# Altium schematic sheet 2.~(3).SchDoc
size 420 x 297 mm
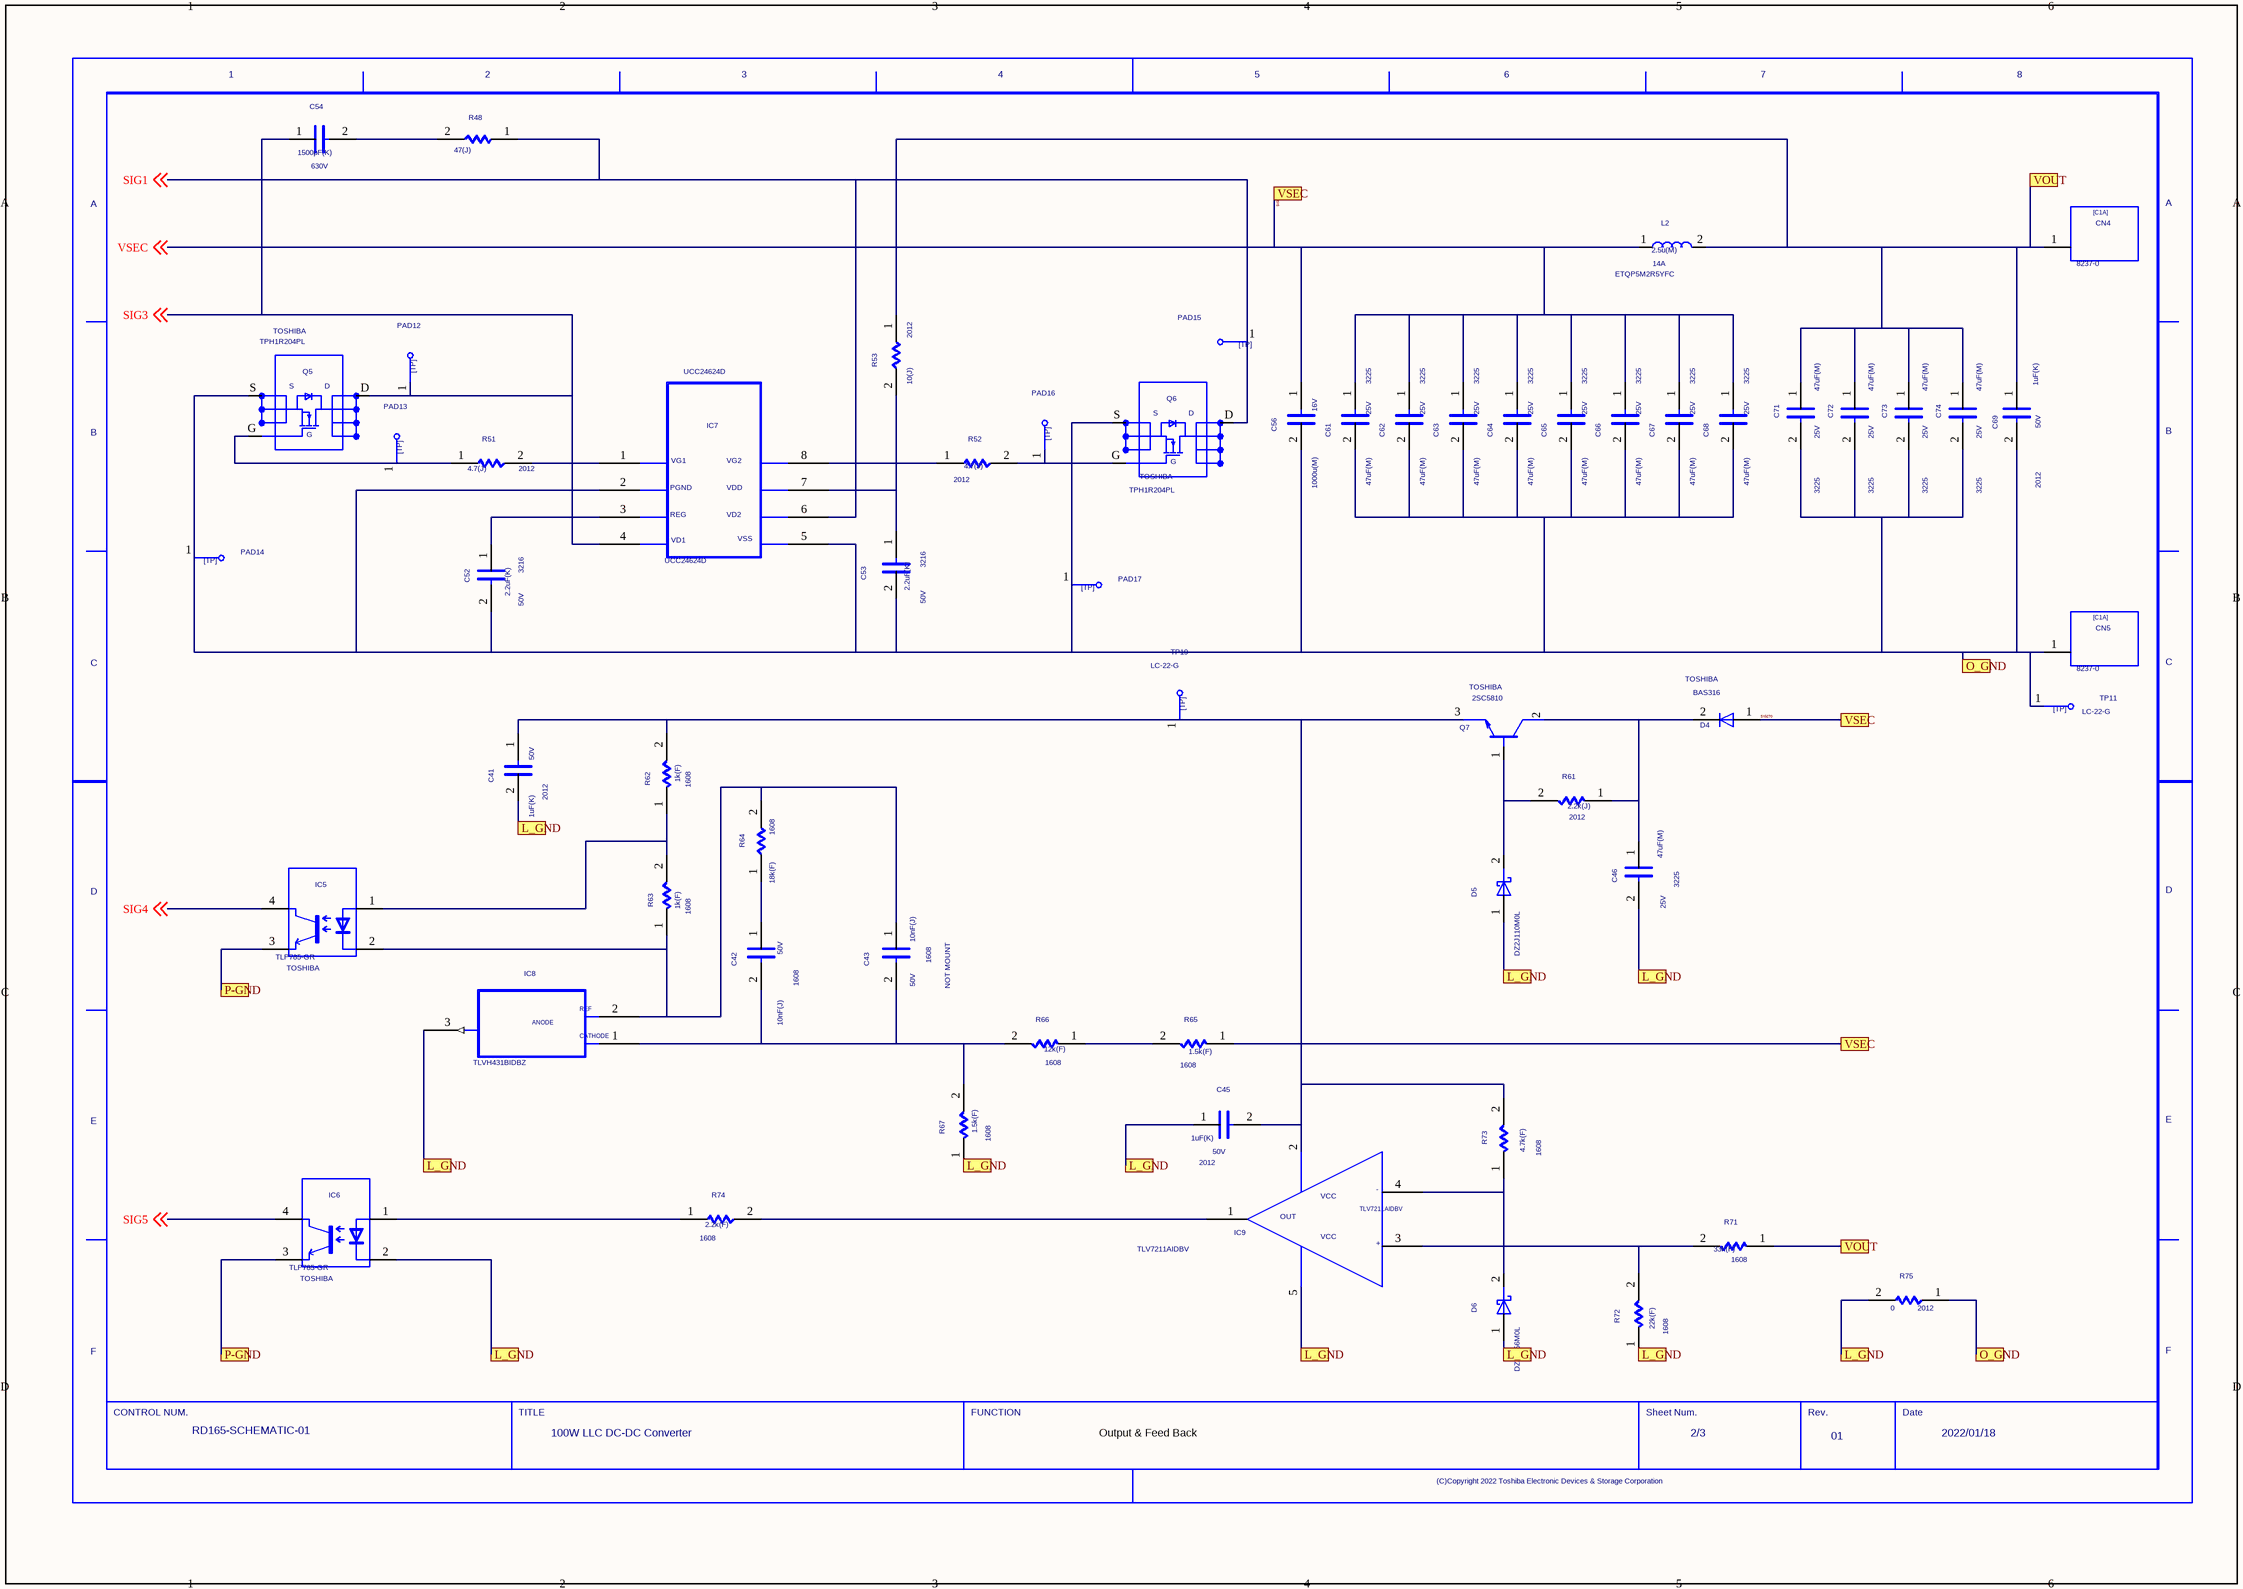
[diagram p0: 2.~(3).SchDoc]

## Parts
C41  SIZECODESMD: 2012  VAL2: 50V  VAL1: 1uF(K)  (hidden comment: C)
C42  SIZECODESMD: 1608  VAL2: 50V  VAL1: 10nF(J)  (hidden comment: C)
C43  NOTMOUNT: NOT MOUNT  SIZECODESMD: 1608  VAL2: 50V  VAL1: 10nF(J)  (hidden comment: C)
C45  SIZECODESMD: 2012  VAL2: 50V  VAL1: 1uF(K)  (hidden comment: C)
C46  SIZECODESMD: 3225  VAL2: 25V  VAL1: 47uF(M)  (hidden comment: C)
C52  SIZECODESMD: 3216  VAL2: 50V  VAL1: 2.2uF(K)  (hidden comment: C)
C53  SIZECODESMD: 3216  VAL2: 50V  VAL1: 2.2uF(K)  (hidden comment: C)
C54  VAL2: 630V  VAL1: 1500pF(K)  (hidden comment: C)
C56  VAL2: 16V  VAL1: 1000u(M)  (hidden comment: C)
C61  SIZECODESMD: 3225  VAL2: 25V  VAL1: 47uF(M)  (hidden comment: C)
C62  SIZECODESMD: 3225  VAL2: 25V  VAL1: 47uF(M)  (hidden comment: C)
C63  SIZECODESMD: 3225  VAL2: 25V  VAL1: 47uF(M)  (hidden comment: C)
C64  SIZECODESMD: 3225  VAL2: 25V  VAL1: 47uF(M)  (hidden comment: C)
C65  SIZECODESMD: 3225  VAL2: 25V  VAL1: 47uF(M)  (hidden comment: C)
C66  SIZECODESMD: 3225  VAL2: 25V  VAL1: 47uF(M)  (hidden comment: C)
C67  SIZECODESMD: 3225  VAL2: 25V  VAL1: 47uF(M)  (hidden comment: C)
C68  SIZECODESMD: 3225  VAL2: 25V  VAL1: 47uF(M)  (hidden comment: C)
C69  SIZECODESMD: 2012  VAL2: 50V  VAL1: 1uF(K)  (hidden comment: C)
C71  SIZECODESMD: 3225  VAL2: 25V  VAL1: 47uF(M)  (hidden comment: C)
C72  SIZECODESMD: 3225  VAL2: 25V  VAL1: 47uF(M)  (hidden comment: C)
C73  SIZECODESMD: 3225  VAL2: 25V  VAL1: 47uF(M)  (hidden comment: C)
C74  SIZECODESMD: 3225  VAL2: 25V  VAL1: 47uF(M)  (hidden comment: C)
CN4  VAL3: 8237-0  (hidden comment: C1A)
CN5  VAL3: 8237-0  (hidden comment: C1A)
D4  USERCOMPTEXT3: TOSHIBA  VAL3: BAS316  (hidden comment: D)
D5  VAL3: DZ2J110M0L  (hidden comment: SBD)
D6  VAL3: DZ2J056M0L  (hidden comment: SBD)
IC5  USERCOMPTEXT3: TOSHIBA  (hidden comment: TLP785-GR)
IC6  USERCOMPTEXT3: TOSHIBA  (hidden comment: TLP785-GR)
IC7  UCC24624D
IC8  VAL3: TLVH431BIDBZ  (hidden comment: HC086_GATE)
IC9  TLV7211AIDBV
L2  VAL3: ETQP5M2R5YFC  VAL2: 14A  VAL1: 2.5u(M)  (hidden comment: L)
PAD12  TP  (value not drawn)
PAD13  TP  (value not drawn)
PAD14  TP  (value not drawn)
PAD15  TP  (value not drawn)
PAD16  TP  (value not drawn)
PAD17  TP  (value not drawn)
Q5  USERCOMPTEXT3: TOSHIBA  (hidden comment: TPH1R204PL)
Q6  USERCOMPTEXT3: TOSHIBA  (hidden comment: TPH1R204PL)
Q7  USERCOMPTEXT3: TOSHIBA  (hidden comment: 2SC5810)
R48  VAL1: 47(J)  (hidden comment: R)
R51  SIZECODESMD: 2012  VAL1: 4.7(J)  (hidden comment: R)
R52  SIZECODESMD: 2012  VAL1: 4.7(J)  (hidden comment: R)
R53  SIZECODESMD: 2012  VAL1: 10(J)  (hidden comment: R)
R61  SIZECODESMD: 2012  VAL1: 2.2k(J)  (hidden comment: R)
R62  SIZECODESMD: 1608  VAL1: 1k(F)  (hidden comment: R)
R63  SIZECODESMD: 1608  VAL1: 1k(F)  (hidden comment: R)
R64  SIZECODESMD: 1608  VAL1: 18k(F)  (hidden comment: R)
R65  SIZECODESMD: 1608  VAL1: 1.5k(F)  (hidden comment: R)
R66  SIZECODESMD: 1608  VAL1: 12k(F)  (hidden comment: R)
R67  SIZECODESMD: 1608  VAL1: 1.5k(F)  (hidden comment: R)
R71  SIZECODESMD: 1608  VAL1: 33k(F)  (hidden comment: R)
R72  SIZECODESMD: 1608  VAL1: 22k(F)  (hidden comment: R)
R73  SIZECODESMD: 1608  VAL1: 4.7k(F)  (hidden comment: R)
R74  SIZECODESMD: 1608  VAL1: 2.2k(F)  (hidden comment: R)
R75  SIZECODESMD: 2012  VAL1: 0  (hidden comment: R)
TP11  VAL3: LC-22-G  (hidden comment: TP)
TP19  VAL3: LC-22-G  (hidden comment: TP)
U?  DATE: 2022/01/18  REVISION: 01  SHEETNUMBER: 2/3  TITLE: 100W LLC DC-DC Converter  DRAWINGNUMBER: RD165-SCHEMATIC-01  (hidden comment: WAKU_DEF100)

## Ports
L_GND, O_GND, P-GND, VOUT, VSEC

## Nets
DN000026: C53.1 IC7.7 R53.2
O_GND: C52.2 C53.2 C56.2 C61.2 C62.2 C63.2 C64.2 C65.2 C66.2 C67.2 C68.2 C69.2 C71.2 C72.2 C73.2 C74.2 CN5.1 IC7.2 IC7.5 PAD14.1 PAD17.1 Q5.S Q6.S R75.1 TP11.1 ; port O_GND
P-GND: IC5.3 IC6.3 ; port P-GND
SIG1: IC7.6 PAD15.1 Q6.D R48.1 ; off-sheet SIG1
SIG3: C54.1 IC7.4 PAD12.1 Q5.D ; off-sheet SIG3
SIG4: IC5.4 ; off-sheet SIG4
SIG5: IC6.4 ; off-sheet SIG5
SIG140: C41.2 C45.1 C46.2 D5.1(A) D6.1(A) IC6.2 IC8.3(A2) IC9.5 R67.1 R72.1 R75.2 ; port L_GND  [also labelled SIG142, SIG149, SIG150, SIG152, SIG156, SIG158, SIG226]
SIG144: C43.1 IC5.2 IC8.2(A0) R63.1 R64.2
SIG154: IC9.3 R71.2 R72.2
SIG160: D5.2(C) Q7.1 R61.2
SIG162: C46.1 D4.2(C) Q7.2 R61.1
SIG166: C52.1 IC7.3
SIG167: IC7.1 R51.2
SIG170: IC7.8 R52.1
SIG172: PAD16.1 Q6.G R52.2
SIG184: IC9.1 R74.2
SIG185: IC6.1 R74.1
SIG210: PAD13.1 Q5.G R51.1
SIG214: C56.1 C61.1 C62.1 C63.1 C64.1 C65.1 C66.1 C67.1 C68.1 D4.1(A) L2.1 R65.1 ; off-sheet VSEC, port VSEC  [also labelled SIG270, VSEC]
SIG215: C69.1 C71.1 C72.1 C73.1 C74.1 CN4.1 L2.2 R53.1 R71.1 ; port VOUT
SIG216: R65.2 R66.1
SIG222: D6.2(C) IC9.4 R73.1
SIG225: C42.2 C43.2 IC8.1(A1) R66.2 R67.2
SIG242: IC5.1 R62.1 R63.2
SIG243: C41.1 C45.2 IC9.2 Q7.3 R62.2 R73.2 TP19.1
SIG244: C42.1 R64.1
SIG247: C54.2 R48.2

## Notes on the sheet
- Output & Feed Back

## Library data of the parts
C41 = C#1: OriginalSymbolOrigin: (2540,7620); CaptureCellPackProp: C##1; RATEDVOLTAGE: 50; MAXGCOUNT: 1; OUMEMAKER: TDK ＴＤＫ; QUADMODEL: CON_1U; FNLEADFREETHET1GT2GMCTH1: 3_2_N; OUMECLASSIFICATION: セラミックコンデンサ; CDBNAME: Chip2012_GS_1; NOMINALCAPACITA: 1u; PMPRODUCTSTYPEG: DA; OUMEMAKERKATAMEI: CGA4J3X7R1H105KT@@; CAPACITANCETOLE: K; CDMASTERCADCELG: KC0159; ADSMODELNAME: s_CGA4J3X7R1H105KT@@
C42 C43 = C: OriginalSymbolOrigin: (2540,7620); RATEDVOLTAGE: 50; MAXGCOUNT: 1; OUMEMAKER: TDK ＴＤＫ; QUADMODEL: CON_10N; FNLEADFREETHET1GT2GMCTH1: 3_2_N; OUMECLASSIFICATION: セラミックコンデンサ; CDBNAME: Chip1608_GS_1; NOMINALCAPACITA: 10n; PMPRODUCTSTYPEG: HEV; OUMEMAKERKATAMEI: CGA3E2C0G1H103JT@@; CAPACITANCETOLE: J; CDMASTERCADCELG: KC0134; ADSMODELNAME: s_CGA3E2C0G1H103JT@@
C45 C69 = C: OriginalSymbolOrigin: (2540,7620); RATEDVOLTAGE: 50; MAXGCOUNT: 1; OUMEMAKER: TDK ＴＤＫ; QUADMODEL: CON_1U; FNLEADFREETHET1GT2GMCTH1: 3_2_N; OUMECLASSIFICATION: セラミックコンデンサ; CDBNAME: Chip2012_GS_1; NOMINALCAPACITA: 1u; PMPRODUCTSTYPEG: DA; OUMEMAKERKATAMEI: CGA4J3X7R1H105KT@@; CAPACITANCETOLE: K; CDMASTERCADCELG: KC0159; ADSMODELNAME: s_CGA4J3X7R1H105KT@@
C46 = C: OriginalSymbolOrigin: (2540,7620); RATEDVOLTAGE: 6.3; MAXGCOUNT: 1; OUMEMAKER: MRT 村田製作所; QUADMODEL: CON_47U; FNLEADFREETHET1GT2GMCTH1: 3_0_N; OUMECLASSIFICATION: セラミックコンデンサ; CDBNAME: Chip3225_GS; NOMINALCAPACITA: 47u; PMPRODUCTSTYPEG: HEV; OUMEMAKERKATAMEI: GCM32ER70J476ME19L@@; CAPACITANCETOLE: M; CDMASTERCADCELG: KC0138; ADSMODELNAME: s_GCM32ER70J476ME19L@@
C52 = C: OriginalSymbolOrigin: (2540,7620); RATEDVOLTAGE: 50; MAXGCOUNT: 1; OUMEMAKER: MRT 村田製作所; QUADMODEL: CON_2.2U; FNLEADFREETHET1GT2GMCTH1: 3_2_N; OUMECLASSIFICATION: セラミックコンデンサ; CDBNAME: Chip3216_GS_1; NOMINALCAPACITA: 2.2u; PMPRODUCTSTYPEG: HEV; OUMEMAKERKATAMEI: GCM31CR71H225KA55L@@; CAPACITANCETOLE: K; CDMASTERCADCELG: KC0137; ADSMODELNAME: s_GCM31CR71H225KA55L@@
C53 = C#1: OriginalSymbolOrigin: (2540,7620); CaptureCellPackProp: C##1; RATEDVOLTAGE: 50; MAXGCOUNT: 1; OUMEMAKER: MRT 村田製作所; QUADMODEL: CON_2.2U; FNLEADFREETHET1GT2GMCTH1: 3_2_N; OUMECLASSIFICATION: セラミックコンデンサ; CDBNAME: Chip3216_GS_1; NOMINALCAPACITA: 2.2u; PMPRODUCTSTYPEG: HEV; OUMEMAKERKATAMEI: GCM31CR71H225KA55L@@; CAPACITANCETOLE: K; CDMASTERCADCELG: KC0137; ADSMODELNAME: s_GCM31CR71H225KA55L@@
C54 = C: OriginalSymbolOrigin: (2540,7620); CDBNAME: ECQE2**3*F_PN
C56 = C#1: OriginalSymbolOrigin: (2540,7620); CaptureCellPackProp: C##1; CDBNAME: PCR1****MCL1GS_NC
C61-C68 = C#1: OriginalSymbolOrigin: (2540,7620); CaptureCellPackProp: C##1; RATEDVOLTAGE: 6.3; MAXGCOUNT: 1; TEMPCHARACTERI2: B; OUMEMAKER: TYD 太陽誘電; QUADMODEL: CON_47U; FNLEADFREETHET1GT2GMCTH1: 3_0_N; OUMECLASSIFICATION: セラミックコンデンサ; CDBNAME: Chip3225_GS; NOMINALCAPACITA: 47u; PMPRODUCTSTYPEG: SV1; OUMEMAKERKATAMEI: JMK325BJ476MM-T; CAPACITANCETOLE: M; CDMASTERCADCELG: DC903A; ADSMODELNAME: s_JMK325BJ476MM_T
C71-C74 = C: OriginalSymbolOrigin: (2540,7620); RATEDVOLTAGE: 6.3; MAXGCOUNT: 1; TEMPCHARACTERI2: B; OUMEMAKER: TYD 太陽誘電; QUADMODEL: CON_47U; FNLEADFREETHET1GT2GMCTH1: 3_0_N; OUMECLASSIFICATION: セラミックコンデンサ; CDBNAME: Chip3225_GS; NOMINALCAPACITA: 47u; PMPRODUCTSTYPEG: SV1; OUMEMAKERKATAMEI: JMK325BJ476MM-T; CAPACITANCETOLE: M; CDMASTERCADCELG: DC903A; ADSMODELNAME: s_JMK325BJ476MM_T
CN4 CN5 = C1A: OUMEPARTTYPE: CN; SAVEAREA0: -2398,-158,22444,15662; SAVECOUNT: 23; TIME: 13:28:28; UPDATEUSER: 19910145; UPDATETIME: 08:46:11; OriginalSymbolOrigin: (5080,12700); RATEDCURRENT: 0; MAXGCOUNT: 1; OUMEMAKER: AMP タイコエレクトロニクスアンプ; FNLEADFREETHET1GT2GMCTH1: N_N_N; OUMECLASSIFICATION: プリント板用角形コネクタ; CDBNAME: 8237-0-05-**-00-00-03-0_ML; OUMEMAKERKATAMEI: 87220-1; CDMASTERCADCELG: CUK0165
D4 = D: SAVEAREA0: -225,-91,12804,7836; SAVECOUNT: 3; TIME: 14:49:55; UPDATEUSER: 19870035; UPDATETIME: 14:20:16; OriginalSymbolOrigin: (5080,5080); CDBNAME: BAS316_TS_A
D5 = SBD: SAVEAREA0: -4630,-153,17114,13055; TIME: 14:49:55; UPDATEUSER: fukuda-y; UPDATETIME: 08:16:22; SAVECOUNT: 9; OriginalSymbolOrigin: (5080,5080); CDBNAME: DZ2J110M0L_PN_A
D6 = SBD: SAVEAREA0: -4630,-153,17114,13055; TIME: 14:49:55; UPDATEUSER: fukuda-y; UPDATETIME: 08:16:22; SAVECOUNT: 9; OriginalSymbolOrigin: (5080,5080); CDBNAME: DZ2J056*0L_PN_A
IC5 IC6 = TLP785-GR: SAVEAREA0: -14986,-1554,37270,22534; TIME: 18:29:30; UPDATEUSER: t5459927; UPDATETIME: 17:04:25; SAVECOUNT: 2; OriginalSymbolOrigin: (5080,17780); CDBNAME: TLP785_TS_1
IC7 = UCC24624D: TIME: 09:07:35; UPDATEUSER: t5459927; UPDATETIME: 09:15:01; SAVECOUNT: 2; SAVEAREA0: -23382,-806,66635,38817; OriginalSymbolOrigin: (7620,35560); CDBNAME: UCC24624D*_TI
IC8 = HC086_GATE: OUMEPARTTYPE: IC; SAVEAREA0: -52989,-44408,93321,62857; TIME: 17:36:35; UPDATEUSER: t5459927; UPDATETIME: 16:48:34; SAVECOUNT: 2; OriginalSymbolOrigin: (7620,15240); MAXGCOUNT: 4; OUMEMAKER: TSB 東芝; GCOUNT: 1; MOUNTINGFORMSMD: SMD; FNLEADFREETHET1GT2GMCTH1: N_N_N; OUMECLASSIFICATION: CMOSロジック; CDBNAME: TLVH43***DBZ*_TI; PROCESS: 74HC; OUMEMAKERKATAMEI: TC74HC86F; CDMASTERCADCELG: DI830B
IC9 = TLV7211AIDBV: SAVECOUNT: 19; SAVEAREA0: -11523,-10867,52370,35975; TIME: 20:02:00; UPDATEUSER: t5459927; UPDATETIME: 08:40:37; OriginalSymbolOrigin: (7620,25400); CDBNAME: TLV7211AIDBVR_TI
L2 = L: OriginalSymbolOrigin: (2540,5080); CDBNAME: ETQP5M***YFC_PN
PAD12-PAD17 = TP: TIME: 16:12:21; UPDATEUSER: fukuda-y; UPDATETIME: 16:18:11; SAVECOUNT: 2; SAVEAREA0: -242,-92,12810,7836; OriginalSymbolOrigin: (0,7620); CDBNAME: TP_I_TH0.5_LC1.1_RC1.2_GS
Q5 Q6 = TPH1R204PL: SAVEAREA0: -12325,8914,25768,24851; TIME: 18:57:44; UPDATEUSER: t5459927; UPDATETIME: 15:06:39; SAVECOUNT: 19; OriginalSymbolOrigin: (2540,20320); CDBNAME: TPH1R204PL_TS_A
Q7 = 2SC5810: DEVICENAME: 2SC2712-Y; SAVECOUNT: 8; SAVEAREA0: -35656,-18339,48402,18661; TIME: 17:21:57; UPDATEUSER: t5459927; UPDATETIME: 15:35:42; OriginalSymbolOrigin: (2540,10160); CDBNAME: 2SC5810_TS
R48 = R: OriginalSymbolOrigin: (5080,5080); VAL2: 1W; CDBNAME: MOS1C****_GS_1
R51 R52 = R: OriginalSymbolOrigin: (5080,5080); MAXGCOUNT: 1; OUMEMAKER: HDK 北陸電気工業; QUADMODEL: RES_4.7; MOUNTINGFORMSMD: SMD; FNLEADFREETHET1GT2GMCTH1: N_N_N; OUMECLASSIFICATION: 表面実装用固定抵抗器; CDBNAME: Chip2012_GS_1; RESISTANCETOLER: J; POWERRATING: 100m; OUMEMAKERKATAMEI: CR1/10 4R7JV; NOMINALRESISTAN: 4.7; VAL2: 400mW; CDMASTERCADCELG: DR910A; ADSMODELNAME: s_CR1_10_4R7JV
R53 = R: OriginalSymbolOrigin: (5080,5080); MAXGCOUNT: 1; OUMEMAKER: NAE パナソニックエレクトロニックデバイス; QUADMODEL: RES_10; MOUNTINGFORMSMD: SMD; FNLEADFREETHET1GT2GMCTH1: N_N_N; OUMECLASSIFICATION: 表面実装用固定抵抗器; CDBNAME: Chip2012_GS_1; RESISTANCETOLER: J; PMPRODUCTSTYPEG: SV1; POWERRATING: 125m; OUMEMAKERKATAMEI: (SV)ERJ6GEYJ100V; NOMINALRESISTAN: 10; VAL2: 400mW; CDMASTERCADCELG: KCK0273; ADSMODELNAME: s__SV_ERJ6GEYJ100V
R61 = R: OriginalSymbolOrigin: (5080,5080); MAXGCOUNT: 1; OUMEMAKER: KOA コーア; QUADMODEL: RES_2.2K; MOUNTINGFORMSMD: SMD; FNLEADFREETHET1GT2GMCTH1: 3_1_N; OUMECLASSIFICATION: 表面実装用固定抵抗器; CDBNAME: Chip2012_GS_1; RESISTANCETOLER: J; PMPRODUCTSTYPEG: HEV; POWERRATING: 250m; OUMEMAKERKATAMEI: SG73P2ATTD222J@@; NOMINALRESISTAN: 2.2K; VAL2: 400mW; CDMASTERCADCELG: KC0135; ADSMODELNAME: s_SG73P2ATTD222J@@
R62 R63 = R: OriginalSymbolOrigin: (5080,5080); MAXGCOUNT: 1; OUMEMAKER: KOA コーア; QUADMODEL: RES_1K; MOUNTINGFORMSMD: SMD; FNLEADFREETHET1GT2GMCTH1: N_N_N; OUMECLASSIFICATION: 表面実装用固定抵抗器; CDBNAME: Chip1608_GS_1; RESISTANCETOLER: F; PMPRODUCTSTYPEG: DME; POWERRATING: 100m; OUMEMAKERKATAMEI: RK73H1JRTTD1001F; NOMINALRESISTAN: 1K; VAL2: 100mW; CDMASTERCADCELG: KC0008; ADSMODELNAME: s_RK73H1JRTTD1001F
R64 = R#1: OriginalSymbolOrigin: (5080,5080); CaptureCellPackProp: R##1; MAXGCOUNT: 1; OUMEMAKER: ROH ロー・; QUADMODEL: RES_18K; MOUNTINGFORMSMD: SMD; FNLEADFREETHET1GT2GMCTH1: 3_1_N; OUMECLASSIFICATION: 表面実装用固定抵抗器; CDBNAME: Chip1608_GS_1; RESISTANCETOLER: F; POWERRATING: 63m; OUMEMAKERKATAMEI: MCR03EZPFX1802; NOMINALRESISTAN: 18K; VAL2: 100mW; CDMASTERCADCELG: DR802R; ADSMODELNAME: s_MCR03EZPFX1802
R65 R67 = R: OriginalSymbolOrigin: (5080,5080); MAXGCOUNT: 1; OUMEMAKER: HDK 北陸電気工業; QUADMODEL: RES_1.5K; MOUNTINGFORMSMD: SMD; FNLEADFREETHET1GT2GMCTH1: 3_1_N; OUMECLASSIFICATION: 表面実装用固定抵抗器; CDBNAME: Chip1608_GS_1; RESISTANCETOLER: F; POWERRATING: 63m; OUMEMAKERKATAMEI: CR1/16 152FV; NOMINALRESISTAN: 1.5K; VAL2: 100mW; CDMASTERCADCELG: DR802R; ADSMODELNAME: s_CR1_16_152FV
R66 = R: OriginalSymbolOrigin: (5080,5080); MAXGCOUNT: 1; OUMEMAKER: HDK 北陸電気工業; QUADMODEL: RES_12K; MOUNTINGFORMSMD: SMD; FNLEADFREETHET1GT2GMCTH1: 3_1_N; OUMECLASSIFICATION: 表面実装用固定抵抗器; CDBNAME: Chip1608_GS_1; RESISTANCETOLER: F; POWERRATING: 63m; OUMEMAKERKATAMEI: CR1/16 123FV; NOMINALRESISTAN: 12K; VAL2: 100mW; CDMASTERCADCELG: DR802R; ADSMODELNAME: s_CR1_16_123FV
R71 = R: OriginalSymbolOrigin: (5080,5080); MAXGCOUNT: 1; OUMEMAKER: ROH ロー・; QUADMODEL: RES_33K; MOUNTINGFORMSMD: SMD; FNLEADFREETHET1GT2GMCTH1: 3_1_N; OUMECLASSIFICATION: 表面実装用固定抵抗器; CDBNAME: Chip1608_GS_1; RESISTANCETOLER: F; POWERRATING: 63m; OUMEMAKERKATAMEI: MCR03EZPFX3302; NOMINALRESISTAN: 33K; VAL2: 100mW; CDMASTERCADCELG: DR802R; ADSMODELNAME: s_MCR03EZPFX3302
R72 = R: OriginalSymbolOrigin: (5080,5080); MAXGCOUNT: 1; OUMEMAKER: NAE パナソニックエレクトロニックデバイス; QUADMODEL: RES_22K; MOUNTINGFORMSMD: SMD; FNLEADFREETHET1GT2GMCTH1: N_N_N; OUMECLASSIFICATION: 表面実装用固定抵抗器; CDBNAME: Chip1608_GS_1; RESISTANCETOLER: F; POWERRATING: 100m; OUMEMAKERKATAMEI: ERJ3EKF2202V; NOMINALRESISTAN: 22K; VAL2: 100mW; CDMASTERCADCELG: KC0008; ADSMODELNAME: s_ERJ3EKF2202V
R73 = R: OriginalSymbolOrigin: (5080,5080); MAXGCOUNT: 1; OUMEMAKER: NAE パナソニックエレクトロニックデバイス; QUADMODEL: RES_4.7K; MOUNTINGFORMSMD: SMD; FNLEADFREETHET1GT2GMCTH1: N_N_N; OUMECLASSIFICATION: 表面実装用固定抵抗器; CDBNAME: Chip1608_GS_1; RESISTANCETOLER: F; PMPRODUCTSTYPEG: DA; POWERRATING: 100m; OUMEMAKERKATAMEI: ERJ3EKF4701V@@; NOMINALRESISTAN: 4.7K; VAL2: 100mW; CDMASTERCADCELG: KCK0234; ADSMODELNAME: s_ERJ3EKF4701V@@
R74 = R: OriginalSymbolOrigin: (5080,5080); MAXGCOUNT: 1; OUMEMAKER: KOA コーア; QUADMODEL: RES_2.2K; MOUNTINGFORMSMD: SMD; FNLEADFREETHET1GT2GMCTH1: 3_1_N; OUMECLASSIFICATION: 表面実装用固定抵抗器; CDBNAME: Chip1608_GS_1; RESISTANCETOLER: F; PMPRODUCTSTYPEG: HEV; POWERRATING: 100m; OUMEMAKERKATAMEI: RK73H1JTTD2201F@@; NOMINALRESISTAN: 2.2K; VAL2: 100mW; CDMASTERCADCELG: KC0133; ADSMODELNAME: s_RK73H1JTTD2201F@@
R75 = R#1: OriginalSymbolOrigin: (5080,5080); CaptureCellPackProp: R##1; MAXGCOUNT: 1; OUMEMAKER: KOA コーア; QUADMODEL: RES_0; MOUNTINGFORMSMD: SMD; FNLEADFREETHET1GT2GMCTH1: 3_2_N; OUMECLASSIFICATION: 表面実装用固定抵抗器; CDBNAME: Chip2012_GS_1; RESISTANCETOLER: X; PMPRODUCTSTYPEG: DME-PC1; POWERRATING: 125m; OUMEMAKERKATAMEI: RK73Z2ATTD; VAL2: 400mW; CDMASTERCADCELG: KCK0211; ADSMODELNAME: s_RK73Z2ATTD
TP11 TP19 = TP: TIME: 16:12:21; UPDATEUSER: fukuda-y; UPDATETIME: 16:18:11; SAVECOUNT: 2; SAVEAREA0: -242,-92,12810,7836; OriginalSymbolOrigin: (0,7620); CDBNAME: LC-22_GS
U? = WAKU_DEF100: PLOTTIME: HH:MM; SAVEAREA0: 198008,-65938,436964,90161; TIME: 14:30:25; UPDATEUSER: t5459927; UPDATETIME: 11:02:38; SAVECOUNT: 4; OriginalSymbolOrigin: (10160,284480)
